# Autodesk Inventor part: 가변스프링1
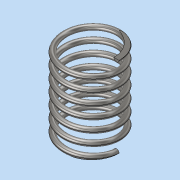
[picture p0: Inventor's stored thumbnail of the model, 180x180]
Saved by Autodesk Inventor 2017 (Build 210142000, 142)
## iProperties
Part Number: 가변스프링1
Material: 스테인레스 스틸
Document SubType Name: Modeling
Designer: MRC
Density: 8 g/cm^3
Appearance: 반연마
Mass: 10.9602 g
Surface Area: 27.6886 cm^2
Volume: 1.37003 cm^3
Author: MRC
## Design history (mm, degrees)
sketch "스케치1"
  geometry: L1 (0, 0)-(10, 0); L2 (10, 0)-(10, 30.363); L3 (10, 30.363)-(0, 30.363); L4 (0, 30.363)-(0, 0); C1 r 1 at (10, 0)
  constraints: 8 end point, 2 parallel, 1 centre point, 1 coincident, 1 horizontal, 1 perpendicular
  dimensions: "d0" = 20 diameter of L2 L4; "d1" = 30.36317 distance of L1.end L2.end (derived); "d2" = 2 diameter of C1
feature "코일1" sketch "스케치1" pitch "d3" = 10; turns "d5" = 7; dims "d4" = 30.36317 (= d1), "d6" = 0, angle "d7" = 90 deg, angle "d8" = 90 deg, "d9" = 0, "d10" = 0
sketch "스케치2"
  geometry: L1 (-15, 30.363)-(15, 30.363); L2 (15, 30.363)-(15, 0); L3 (15, 0)-(-15, 0); L4 (-15, 0)-(-15, 30.363); L5 (0, 30.363)-(0, 0) reference; 2 further points
  constraints: 8 end point, 2 midpoint, 2 parallel, 1 coincident, 1 horizontal, 1 perpendicular
  dimensions: "d11" = 30 distance of L1.start L1.end
extrude "돌출1" sketch "스케치2" stored distance "d12" = 0; taper "d13" = 0 deg
node "솔리드1"
